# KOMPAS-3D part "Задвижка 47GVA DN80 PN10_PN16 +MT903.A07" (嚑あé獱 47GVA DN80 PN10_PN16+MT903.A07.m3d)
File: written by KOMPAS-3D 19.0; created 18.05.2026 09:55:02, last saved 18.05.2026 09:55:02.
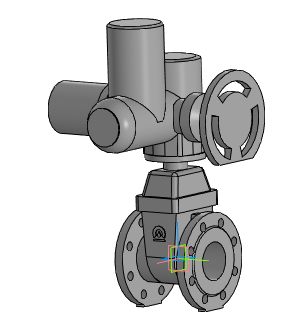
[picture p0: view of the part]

Document properties: Автор: Энергия; Полное имя файла: ..\Задвижка 47GVA DN50_DN1000+MT903.A\Задвижка 47GVA DN80 PN10_PN16+MT903.A07.a3d

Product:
- Part/product: Задвижка 47GVA DN80 PN10_PN16 +MT903.A07
    Масса: 91.9397
  - Body: Электропривод МТ903.А07 без блока управления
      Масса: 65.4738
  - Body: Задвижка 47GVA DN80 PN10_PN16 без исполнит. мех.
      Масса: 26.4658

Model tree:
1. Операция без истории:1
2. Операция без истории:2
